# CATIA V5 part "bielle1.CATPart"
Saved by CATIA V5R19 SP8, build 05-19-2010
Part number: Pièce1
Bounding box of the stored display mesh (mm): x -20 to 20, y 51.124 to 210.571, z -647.162 to 12.484
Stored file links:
  G:\EU_thinkMotion\CFAO_2010\SIL_groupe1\SIL_groupe1\A reprendre\lalpha\lalpha\Alpha.mécanisme\bielle1.CATPart
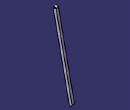
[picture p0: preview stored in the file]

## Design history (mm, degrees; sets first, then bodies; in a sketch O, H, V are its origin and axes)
Body1 (main body)
  Line1: stored without definition
  Line2: stored without definition
  Sketch1 on Line1, origin (0, 0, 299.209), H (0, 0.2076, -0.9782), V (0, 0.9782, 0.2076)
    line L1 (305.8821, 12.5) -> (954.6779, 12.5)
    line L2 (954.6779, -12.5) -> (305.8821, -12.5)
    arc A1 centre (954.6779, 0) radius 12.5 from (954.6779, -12.5) to (954.6779, 12.5) ccw
    arc A2 centre (305.8821, 0) radius 12.5 from (305.8821, 12.5) to (305.8821, -12.5) ccw
    circle A3 centre (305.8821, 0) radius 5
    horizontal: L1 H, L2 H
    tangency: A1 L1, A2 L1
  Pad1: profile Sketch1, direction (1, 0, 0), length 20
  Line3: stored without definition
  Line4: stored without definition
  Sketch2 on Line3, origin (0, 0, 299.209), H (0, 0.2076, -0.9782), V (0, 0.9782, 0.2076)
    circle A1 centre (954.7035, 0) radius 5
    point P1 (954.7035, 0)
    coincidence: P1 H
  Pad2: profile Sketch2, direction (-1, 0, 0), length 20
